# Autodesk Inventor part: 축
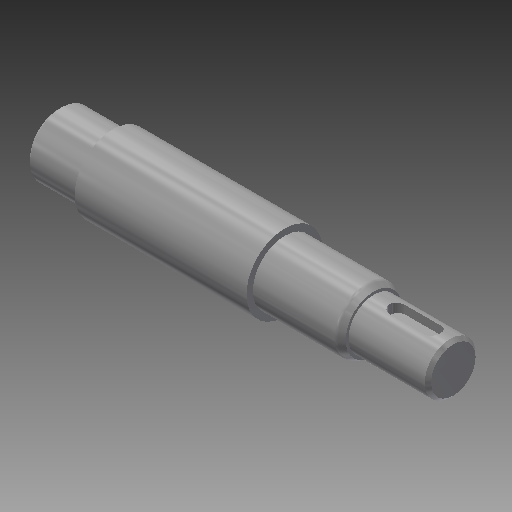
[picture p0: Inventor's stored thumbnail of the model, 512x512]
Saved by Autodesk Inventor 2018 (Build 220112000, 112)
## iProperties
Created: 2016-06
Part Number: 축
Material: 강철, 연강
Document SubType Name: Modeling
Designer: mduedu
Density: 7.86 g/cm^3
Appearance: 강철
Author: mduedu
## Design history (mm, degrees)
sketch "스케치1"
  geometry: L1 (-62, 0)-(62, 0); L2 (-62, 0)-(-62, 10); L3 (-62, 10)-(-45, 10); L4 (-45, 10)-(-45, 12); L5 (-45, 12)-(9, 12); L6 (9, 12)-(9, 10); L7 (9, 10)-(37, 10); L8 (37, 10)-(37, 8); L9 (37, 8)-(62, 8); L10 (62, 8)-(62, 0); 2 further points
  constraints: 20 end point, 5 parallel, 2 perpendicular, 1 coincident, 1 collinear, 1 horizontal, 1 midpoint, 1 vertical
  dimensions: "d0" = 124 distance of L1.start L1.end; "d2" = 16 diameter of L9 L1; "d3" = 20 diameter of L7 L1; "d4" = 24 diameter of L5 L1; "d5" = 20 diameter of L3 L1; "d6" = 17 distance of L2.end L3.end; "d7" = 25 distance of L8.end L9.end; "d8" = 53 distance from line of L5.end L10
revolve "회전1" sketch "스케치1" stored, may be unused: angle "d9" = 90 deg
chamfer "모따기1" distance "d10" = 2; stored, may be unused: second distance "d11" = 2, angle "d12" = 30 deg
fillet "모깎기1" dims "d13" = 2
node "작업 평면1"
sketch "스케치2"
  geometry: L1 (-5, 2.5)-(6, 2.5); L2 (6, -2.5)-(-5, -2.5); L3 (-5, 0)-(6, 0); L4 (-12.5, 8.845)-(-12.5, -8.845) reference; A1 r 2.5 centre (-5, 0) between (-5, 2.5) and (-5, -2.5); A2 r 2.5 centre (6, 0) between (6, -2.5) and (6, 2.5); 1 further point
  constraints: 6 end point, 4 point on circle, 3 tangent, 2 centre point, 2 parallel, 1 horizontal, 1 horizontal alignment
  dimensions: "d14" = 5 distance edge to line of A1 L4; "d15" = 5 distance between parallel lines of L2 L1; "d16" = 16 dimension on A2 A1
extrude "돌출1" cut sketch "스케치2" distance "d17" = 3; taper "d18" = 0 deg
chamfer "모따기2" distance "d19" = 1; stored, may be unused: second distance "d20" = 2, angle "d21" = 30 deg
sketch "스케치3"
  geometry: L1 (-37, -8)-(-61, -8) reference; L2 (-62, -7)-(-62, 7) reference; L3 (-38.5, -8)-(-40, -6.5); L4 (-40, -6.5)-(-40, -8); L5 (-38.5, -8)-(-40, -8); 1 further point
  constraints: 6 end point, 2 point on line, 1 collinear, 1 vertical
  dimensions: "d22" = 45 deg angle of L4 L3; "d23" = 22 distance between parallel lines of L2 L4; "d24" = 3 diameter of L3.start L4
revolve "회전2" stored, may be unused: angle "d25" = 90 deg
node "작업점1"
sketch "스케치4"
  geometry: 1 further point
hole "구멍1" sketch "스케치4" at (0, 0) diameter "d26" = 3.242; stored, may be unused: countersink angle "d30" = 90 deg, drill point angle "d32" = 120 deg; dims "d27" = 8, "d28" = 4, "d29" = 2, "d31" = 11
chamfer "모따기3" distance "d33" = 2; stored, may be unused: second distance "d34" = 2, angle "d35" = 30 deg
node "솔리드1"
